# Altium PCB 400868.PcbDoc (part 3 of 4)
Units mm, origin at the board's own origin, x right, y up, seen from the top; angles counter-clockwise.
Board outline 117 x 63.5 mm, 4 copper layers (Top Layer, Mid-Layer 1, Mid-Layer 2, Bottom Layer), stack 1.58 mm thick; 211 components, 153 nets, 878 pads, 1351 vias.
Unrouted connection lines stored in the file: 16.
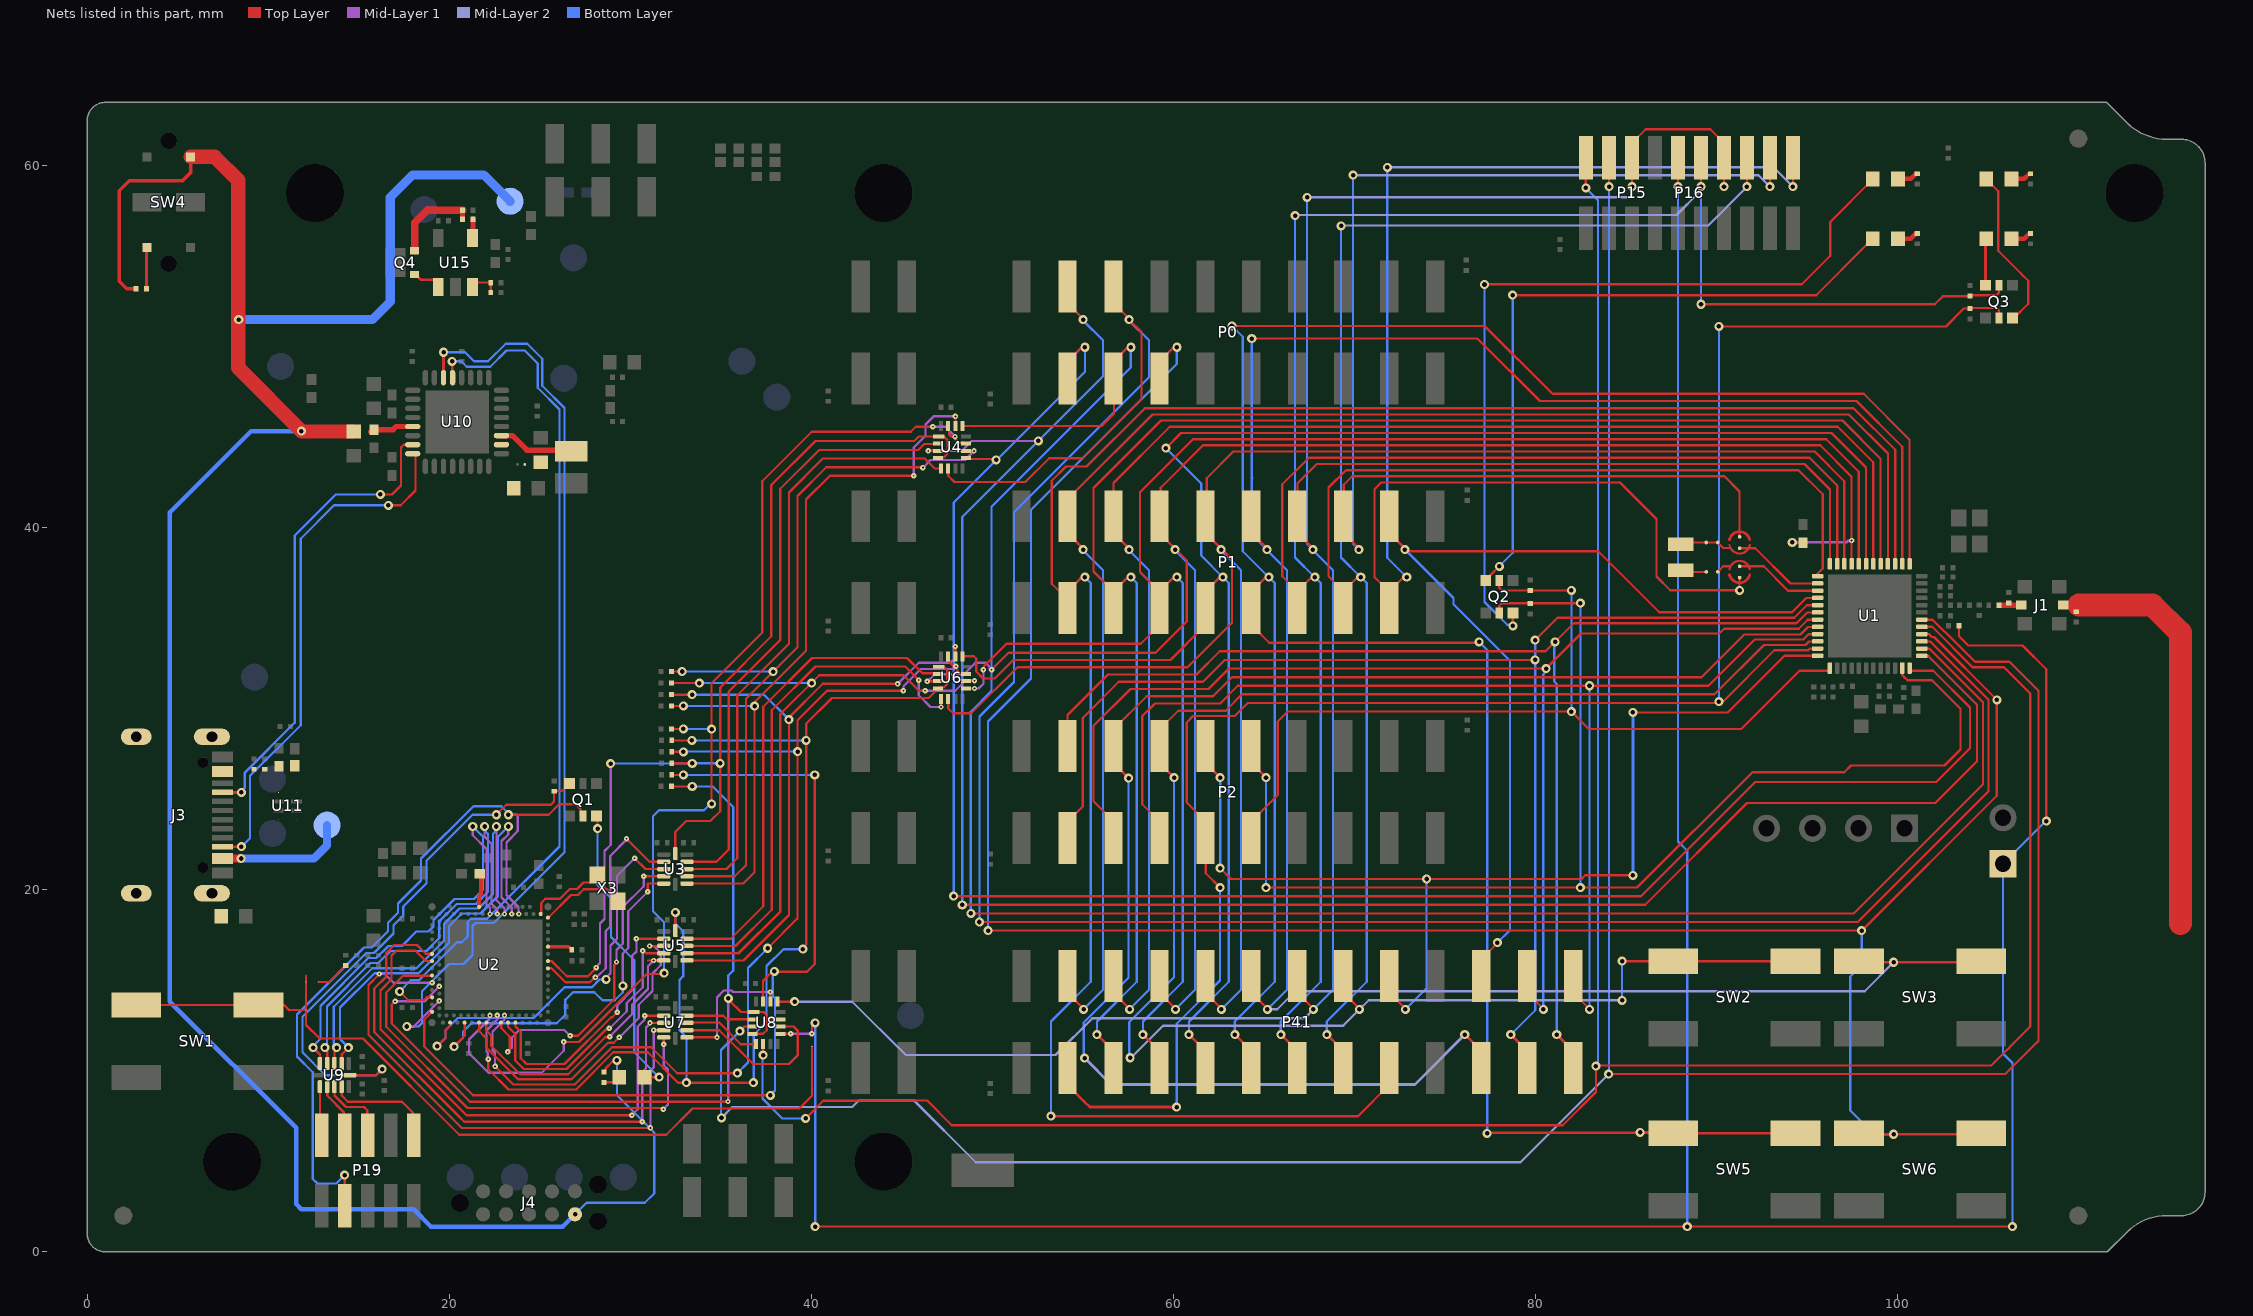
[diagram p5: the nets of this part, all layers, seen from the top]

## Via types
v1: diameter 0.5, hole 0.25, Top Layer to Bottom Layer, tented both sides, 1252 vias
v2: diameter 0.3, hole 0.1, Top Layer to Mid-Layer 1, tented top, 72 vias
v3: diameter 0.3, hole 0.1, Top Layer to Mid-Layer 1, tented both sides, 18 vias
v4: diameter 0.5, hole 0.25, Top Layer to Bottom Layer, tented bottom, 9 vias

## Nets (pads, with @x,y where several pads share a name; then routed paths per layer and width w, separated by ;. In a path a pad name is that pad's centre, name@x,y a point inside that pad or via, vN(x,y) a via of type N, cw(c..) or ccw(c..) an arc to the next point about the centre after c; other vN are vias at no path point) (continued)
NetC45_2: C45.2 U2.A13 | length 1.9
  Top Layer w0.225: U2.A13@21.66,19.064 21.66,19.644 21.77,19.754 C45.2@21.77,20.891
NetC59_1: C59.1 J3.SHLD
NetC82_1: C82.1 R48.2 U15.3 | length 1.7
  Top Layer w0.125: U15.3@21.3,53.3 21.3,53.313 21.538,53.55 C82.1@22.3,53.55 R48.2@22.3,53
NetL8_2: L8.2 U10.3 | length 4.2
  Top Layer w0.3: U10.3@22.892,45.096 23.492,45.096 24.292,44.296 L8.2@26.749,44.296
NetLD1_1: LD1.1 Q1.6 | length 16.7
  Top Layer w0.125: Q1.6@28.151,24.083 28.204,24.03 v1(28.204,23.381) ; LD1.1@30.865,9.716 30.929,9.652 v1(31.6,9.652)
  Top Layer w0.15: LD1.1@30.802,9.652 LD1.1@30.865,9.716
  Bottom Layer w0.125: v1(28.204,23.381) 28.204,20.271 28.942,19.533 28.942,17.39 30.225,16.107 30.225,11.027 v1(31.6,9.652)
NetLD1_2: LD1.2 R5.1 | length 1.4
  Top Layer w0.125: LD1.2@29.12,9.937 LD1.2@29.405,9.652
  Top Layer w0.15: R5.1@28.56,9.367 29.12,9.367 LD1.2@29.405,9.652
NetLD2_1: LD2.1 Q2.6 | length 45.3
  Top Layer w0.125: v1(77.2,53.441) 77.209,53.45 94.725,53.45 96.3,55.025 96.3,56.898 98.651,59.25 LD2.1@98.651,59.275 ; v1(78.767,34.579) Q2.6@78.767,35.289
  Bottom Layer w0.125: v1(77.2,53.441) 77.2,35.9 78.46,34.64 78.706,34.64 v1(78.767,34.579)
NetLD2_2: LD2.2 R19.1 | length 1.2
  Top Layer w0.25: LD2.2@100.048,59.275 100.746,59.275 101.021,59.55 101.09,59.55 R19.1@101.1,59.56
NetLD3_1: LD3.1 Q3.6 | length 8.9
  Top Layer w0.125: LD3.1@104.914,59.275 104.914,59.25 105.575,58.588 105.575,55.3 106.845,54.03 ; Q3.6@106.482,51.625 107.232,52.375 107.232,53.643 106.843,54.032
NetLD3_2: LD3.2 R20.1 | length 1.2
  Top Layer w0.25: LD3.2@106.311,59.275 107.008,59.275 107.283,59.55 107.352,59.55 R20.1@107.362,59.56
NetLD4_1: LD4.1 Q2.3 | length 37.5
  Top Layer w0.125: Q2.3@77.504,37.089 77.504,37.363 v1(78.017,37.875) ; v1(78.75,52.85) 95.527,52.85 98.308,55.631 98.333,55.631 98.651,55.95 LD4.1@98.651,55.975
  Bottom Layer w0.125: v1(78.017,37.875) 78.767,38.625 78.767,52.833 v1(78.75,52.85)
NetLD4_2: LD4.2 R21.1 | length 1.2
  Top Layer w0.25: LD4.2@100.048,55.975 100.746,55.975 101.021,56.25 101.09,56.25 R21.1@101.1,56.26
NetLD5_1: LD5.1 Q3.3 | length 2.6
  Top Layer w0.15: Q3.3@104.875,53.4 104.875,55.936 LD5.1@104.914,55.975
NetLD5_2: LD5.2 R22.1 | length 1.2
  Top Layer w0.25: LD5.2@106.311,55.975 107.008,55.975 107.283,56.25 107.352,56.25 R22.1@107.362,56.26
NetQ1_3: Q1.3 R8.1 U9.12 | length 30.6
  Top Layer w0.125: U9.12@14.514,9.765 15.965,9.765 v1(16.3,10.1) ; v1(22.608,24.15) 23.158,24.7 25.625,24.7 25.8,24.875 R8.1@25.8,25.449 ; R8.1@25.8,25.455 26.223,25.455 26.478,25.71 Q1.3@26.651,25.71
  Bottom Layer w0.125: v1(16.3,10.1) 15.965,9.765 13.16,9.765 11.9,11.025 11.9,12.983 15.429,16.512 15.848,16.512 16.925,17.589 16.925,18.05 17.463,18.588 17.463,19.081 18.753,20.372 18.753,21.603 21.3,24.15 v1(22.608,24.15)
NetQ4_1: Q4.1 U15.1 | length 1.7
  Top Layer w0.15: Q4.1@18.1,54 18.15,54 18.45,53.7 19.175,53.7 19.4,53.475 U15.1@19.4,53.3
NetQ4_2: Q4.2 R25.1 R35.2 | length 5
  Top Layer w0.27: R35.2@20.75,57.05 R25.1@20.75,57.55
  Top Layer w0.4: Q4.2@18.1,55.3 18.1,56.85 18.8,57.55 R25.1@20.75,57.55
NetR7_1: R7.1 U2.L31 | length 1.4
  Top Layer w0.187: U2.L31@25.46,16.864 26.598,16.864 26.719,16.743 26.734,16.743 26.775,16.702 R7.1@26.775,16.687
NetR23_1: R23.1 SB8.2 | length 1.9
  Top Layer w0.125: SB8.2@12.8,14.91 13.38,14.91 14.285,15.815 R23.1@14.3,15.815
NetR32_1: R32.1 U3.7 U4.14 | length 42.3
  Top Layer w0.125: R32.1@32.301,30.158 v1(32.941,30.158) ; U3.7@33.14,20.35 36.256,20.35 36.872,20.966 ; v1@36.872,30.153 36.872,30.358 39.722,33.208 39.722,41.563 41.037,42.877 v2(45.672,42.877) ; 36.875,20.966 v1(36.875,30.153) ; U4.14@47.968,45.632 U4.14@47.975,45.625 v2(47.974,46.156)
  Mid-Layer 1 w0.125: v2(45.672,42.877) 45.672,44.437 46.322,45.088 46.322,45.713 46.766,46.156
  Mid-Layer 1 w0.127: 46.766,46.156 v2(47.974,46.156)
  Bottom Layer w0.125: v1(32.941,30.158) v1@36.872,30.158
NetR35_1: R35.1 U15.4 | length 1.1
  Top Layer w0.27: U15.4@21.3,56 21.32,56.02 R35.1@21.32,57.05
NetR36_1: R36.1 SW4.3 | length 2.3
  Top Layer w0.15: R36.1@3.285,53.2 3.285,55.452 SW4.3@3.321,55.488
NetR56_1: R56.1 U5.7 U6.14 | length 36.4
  Top Layer w0.125: R56.1@32.301,30.783 v1(33.428,30.783) ; U5.7@33.14,16.1 36.26,16.1 38.775,18.615 38.775,29.523 40.64,31.388 44.762,31.388 v2(44.775,31.375) ; U6.14@47.954,32.918 U6.14@47.961,32.911
  Top Layer w0.127: U6.14@47.961,32.911 v2@47.961,33.442
  Mid-Layer 1 w0.125: v2(44.775,31.375) 45.952,32.552 47.288,32.552 47.289,32.553
  Mid-Layer 1 w0.127: 47.289,32.553 47.704,32.553 47.974,32.823 v2@47.974,33.431
  Bottom Layer w0.125: v1(33.428,30.783) 37.397,30.783 v1(38.775,29.405)
  other v2: 47.96,33.442
NetSB3_2: SB3.2 X2.2 | length 1.4
  Top Layer w0.125: X2.2@88.05,39.095 88.144,39.189 SB3.2@89.456,39.189
NetSB4_2: SB4.2 X2.1 | length 1.4
  Top Layer w0.125: X2.1@88.05,37.645 88.131,37.563 SB4.2@89.456,37.563
NetU2_B30: U2.B30 X3.3 | length 4.4
  Top Layer w0.125: U2.B30@25.06,18.664 25.079,18.684 25.079,18.754 25.085,18.76 25.085,19.273 25.315,19.502 26.123,19.502 26.67,20.05 27.075,20.05 27.125,20.1 27.431,20.406 27.818,20.406 28.181,20.769 X3.3@28.181,20.819
NetU2_C31: U2.C31 X3.1 | length 4.3
  Top Layer w0.125: U2.C31@25.46,18.464 25.485,18.464 26.735,19.715 27.126,19.715 27.443,20.031 27.747,20.031 28.718,20.031 X3.1@29.031,19.719
NetU3_10: U3.10 U4.2 | length 33.4
  Top Layer w0.125: U3.10@33.14,21.55 34.769,21.55 35.447,22.228 ; 35.45,22.228 35.45,30.951 38.297,33.798 38.297,42.153 40.447,44.302 45.923,44.302 46.252,44.632 46.981,44.632 U4.2@47,44.65
NetU5_10: U5.10 U6.2 | length 27.1
  Top Layer w0.125: U5.10@33.14,17.3 35.562,17.3 37.35,19.088 37.35,30.113 40.049,32.813 45.3,32.813 46.152,31.961 46.863,31.961 46.875,31.949 U6.2@46.985,31.949
NetU7_7: U7.7 U8.14 | length 7.5
  Top Layer w0.127: U7.7@33.14,11.85 v2(34.8,11.85) ; U8.14@37.745,13.825 v2@37.745,14.355
  Mid-Layer 1 w0.127: v2(34.8,11.85) 34.8,14.059 35.179,14.439 35.607,14.439 35.689,14.356 v2(37.744,14.356)
NetU7_8: U7.8 U8.10 | length 9.5
  Top Layer w0.127: U7.8@33.14,12.25 34.926,12.25 36.801,10.375 38.772,10.375 39.27,10.873 39.27,12.2 39.02,12.45 U8.10@38.32,12.45
NetU7_9: U7.9 U8.5 | length 4.3
  Top Layer w0.125: U7.9@33.14,12.65 33.16,12.67 34.925,12.67 36.12,11.475 U8.5@36.945,11.475
NetU7_10: U7.10 U8.2 | length 3.7
  Top Layer w0.125: U7.10@33.14,13.05 35.149,13.05 35.349,12.85 U8.2@36.77,12.85
nRF54_NRESET: P3.1 P15.10 P16.10 R1.2 SB1.1 U8.9 | length 177.4
  Top Layer w0.125: U8.9@38.32,12.05 38.321,12.051 v2(38.872,12.051) ; v2(40.045,12.05) 40.045,12.47 v1(40.225,12.65) ; v1@40.148,1.4 v1(88.4,1.4) v1@106.4,1.4 ; v1(87.89,58.844) P15.10@87.89,60.509 ; R1.2@103.411,34.579 103.411,34.011 103.923,33.5 106.925,33.5 108.238,32.187 v1(108.238,23.8)
  Mid-Layer 1 w0.125: v2(38.872,12.051) v2@40.044,12.051
  Bottom Layer w0.125: v1(40.224,1.4) 40.225,1.401 v1(40.225,12.65) ; v1(87.89,58.844) 87.89,22.671 88.4,22.161 v1(88.4,1.4) ; v1(106.364,1.4) 106.364,10.436 105.845,10.955 P3.1@105.845,21.443 108.202,23.8 v1(108.238,23.8)
P0.00: P0.3 U1.24 U4.9 | length 101.8
  Top Layer w0.125: v1(47.875,19.65) 85.85,19.65 92.162,25.962 102.16,25.962 104.025,27.827 104.025,30.075 101.995,32.105 U1.24@100.68,32.105 ; U4.9@48.55,43.85 48.597,43.803 50.172,43.803 v1(50.225,43.75) ; P0.3@54.363,49.386 54.88,49.903
  Bottom Layer w0.125: v1(47.875,19.65) 47.875,41.4 v1(50.225,43.75) 50.25,43.75 55.125,48.625 v1(55.125,49.975)
P0.01: P0.4 U1.25 U4.3 | length 111.3
  Top Layer w0.125: v1(48.35,19.175) 86.075,19.175 91.7,24.8 102.1,24.8 104.403,27.103 104.403,30.231 101.755,32.878 101.755,32.891 101.717,32.93 U1.25@101.505,32.93 ; P0.4@54.164,52.413 P0.4@54.189,52.388 ; P0.4@54.189,53.223 P0.4@54.189,52.388 ; v1@55.025,51.552 P0.4@54.189,52.388
  Top Layer w0.127: v2(46.469,44.25) U4.3@47,44.25
  Mid-Layer 1 w0.127: v2(46.469,44.25) 48.325,44.25 48.875,44.8 v1(52.55,44.8)
  Bottom Layer w0.125: v1(48.35,19.175) 48.35,40.6 v1(52.55,44.8) 56.125,48.375 56.125,50.356 v1@55.025,51.456
  other v1: 55.025,51.5
P0.02: P0.5 U1.26 U4.13 | length 114.6
  Top Layer w0.125: U4.13@48.375,45.625 56.037,45.625 56.729,46.317 P0.5@56.729,48.778 ; v1(48.825,18.7) 97.6,18.7 104.733,25.833 104.733,30.367 101.78,33.32 101.515,33.32 U1.26@101.505,33.33 ; P0.5@56.903,49.386 57.42,49.903
  Bottom Layer w0.125: v1(48.825,18.7) 48.825,29.842 49.962,30.98 49.962,41.162 57.665,48.865 v1(57.665,49.975)
P0.03: P0.6 U1.27 U4.6 | length 126.1
  Top Layer w0.125: U4.6@47.575,43.275 47.575,42.875 47.925,42.525 51.825,42.525 53.15,43.85 55,43.85 58.25,47.1 58.25,50.815 v1(57.565,51.5) ; v1(49.3,18.225) 97.825,18.225 105.047,25.447 105.047,30.498 101.824,33.72 101.515,33.72 U1.27@101.505,33.73 ; P0.6@56.704,52.413 P0.6@56.729,52.388 ; P0.6@56.729,53.223 P0.6@56.729,52.388 ; v1@57.6,51.517 P0.6@56.729,52.388
  Bottom Layer w0.125: v1(49.3,18.225) 49.3,29.575 51.213,31.488 51.213,40.863 58.665,48.315 58.665,50.356 v1@57.565,51.456
P0.04: P0.7 SW6.2 U1.28 | length 127.9
  Top Layer w0.125: v1(49.775,17.75) 98.05,17.75 105.5,25.2 v1(105.5,30.5) 102.03,33.97 101.91,33.97 101.751,34.13 U1.28@101.505,34.13 ; P0.7@59.443,49.386 59.96,49.903 ; SW6.2@96.887,6.558 96.945,6.5 103.579,6.5 SW6.2@103.637,6.558
  Top Layer w0.15: P0.7@59.269,47.549 P0.7@59.269,48.578
  Bottom Layer w0.125: v1(49.775,17.75) 49.775,29.3 52.15,31.675 52.15,41 60.205,49.055 v1(60.205,49.975) ; v1(98.034,17.75) 98.034,15.841 97.4,15.207 97.4,7.815 98.715,6.5 v1(99.8,6.5)
P1.00: P1.3 P41.17 U1.39 | length 114.4
  Top Layer w0.125: v1@53.3,7.5 70.211,7.5 P41.17@71.944,9.233 ; P1.3@54.164,35.56 54.164,36.039 53.3,36.903 53.3,42.6 54.085,43.385 55.214,43.385 58.438,46.609 97.591,46.609 99.89,44.31 U1.39@99.89,38.164
  Top Layer w0.15: P1.3@54.164,36.039 54.164,36.487 54.885,37.208 55.058,37.208 v1(55.125,37.275)
  Bottom Layer w0.125: 53.25,7.8 53.25,12.725 55.45,14.925 55.45,36.95 v1(55.125,37.275)
  other v1: 53.25,7.5
P1.01: P1.4 P41.4 U1.40 | length 85.7
  Top Layer w0.125: P41.4@54.164,15.24 54.164,14.313 55.05,13.427 v1(55.05,13.4) ; v1(55.025,38.8) 55.025,38.852 54.164,39.713 P1.4@54.164,40.64 54.2,40.676 54.2,41.603 54.597,42 58.864,46.267 97.329,46.267 99.49,44.105 U1.40@99.49,38.165
  Bottom Layer w0.125: v1(55.025,38.8) 55.025,38.756 56.125,37.656 56.125,14.475 v1(55.05,13.4)
P1.02: P1.5 P41.5 U1.41 | length 87.6
  Top Layer w0.125: P1.5@56.704,35.56 P1.5@56.704,36.487 ; v1(57.665,37.275) 57.593,37.203 57.42,37.203 P1.5@56.704,36.487 ; U1.41@99.08,38.155 99.08,43.82 96.976,45.924 59.324,45.924 55.6,42.2 55.6,37.591 P1.5@56.704,36.487
  Top Layer w0.15: v1@55.791,12 P41.5@56.704,11.087
  Bottom Layer w0.125: v1(55.79,12) 55.79,12.725 57.99,14.925 57.99,36.95 v1(57.665,37.275)
P1.03: P1.6 P41.6 U1.42 | length 80.1
  Top Layer w0.125: P41.6@56.704,14.313 v1@57.59,13.427 ; P1.6@56.704,39.713 v1@57.565,38.852 ; P1.6@56.704,40.64 56.704,42.475 59.811,45.582 96.718,45.582 98.68,43.62 U1.42@98.68,38.155
  Bottom Layer w0.125: v1@57.565,38.756 58.665,37.656 58.665,14.475 v1(57.59,13.4)
  other v1: 57.565,38.8
P1.04: P1.7 P41.7 U1.44 U6.9 | length 96
  Top Layer w0.125: U6.9@48.55,31.125 v2(49.025,31.125) ; v2(49.517,32.163) 49.551,32.196 49.551,32.351 50.8,33.6 58.211,33.6 59.244,34.633 P1.7@59.244,35.56 59.244,36.259 59.443,36.458 59.443,36.686 59.96,37.203 60.133,37.203 v1(60.205,37.275) ; P1.7@59.244,36.487 58.17,37.561 58.17,41.97 61.097,44.897 96.084,44.897 97.88,43.1 U1.44@97.88,38.155
  Top Layer w0.15: v1@58.331,12 P41.7@59.244,11.087
  Mid-Layer 1 w0.125: v2(49.025,31.125) 49.026,31.126 49.251,31.126 49.517,31.392 v2(49.517,32.163)
  Bottom Layer w0.125: v1(58.33,12) 58.33,12.725 60.53,14.925 60.53,36.95 v1(60.205,37.275)
P1.05: C41.2 P1.8 P41.8 U1.45 U6.3 | length 101.5
  Top Layer w0.125: v2(49.967,32.163) 50.905,33.1 59.025,33.1 60.75,34.825 60.75,38.2 v1@60.101,38.849 ; P41.8@59.244,14.313 v1@60.13,13.427 ; P1.8@59.244,39.713 59.504,39.454 59.693,39.264 v1@60.105,38.852 ; P1.8@59.244,40.64 59.244,39.706 59.5,39.45 59.507,39.45 59.69,39.267 P1.8@59.69,39.26 ; P1.8@59.309,40.363 59.309,42.209 61.655,44.555 95.745,44.555 97.48,42.82 v2(97.48,39.3) ; v2@97.409,39.309 97.409,39.262 97.48,39.19 U1.45@97.48,38.155
  Top Layer w0.127: v2(46.414,31.514) 46.426,31.525 U6.3@47,31.525
  Top Layer w0.15: v1(94.2,39.2) C41.2@94.779,39.2 ; C41.2@94.779,39.3 C41.2@94.804,39.275
  Mid-Layer 1 w0.127: v2(46.414,31.514) 46.425,31.514 46.825,31.914 48.439,31.914 49.064,32.539 49.639,32.539 49.856,32.322 49.856,32.178 v2@49.889,32.145 ; v2@49.964,32.167 v2(49.967,32.163)
  Mid-Layer 1 w0.15: v1(94.2,39.2) 97.2,39.2 97.271,39.271 97.389,39.271 v2@97.418,39.3
  Bottom Layer w0.125: v1@60.105,38.756 61.205,37.656 61.205,14.475 v1(60.13,13.4)
  other v1: 60.105,38.8
P1.06: P1.9 P41.9 U1.43 U6.13 | length 98.7
  Top Layer w0.125: U6.13@48.361,32.911 48.989,32.911 49.118,32.782 49.118,32.057 49.495,31.68 50.144,31.68 51.164,32.7 59.851,32.7 P1.9@61.655,34.504 ; v1(59.6,44.4) 60.439,45.239 96.371,45.239 98.28,43.33 U1.43@98.28,38.155 ; P1.9@61.784,35.56 61.825,35.601 61.825,35.675 61.85,35.65 61.85,36.553 62.5,37.203 62.673,37.203 v1(62.745,37.275)
  Top Layer w0.15: v1@60.871,12 P41.9@61.784,11.087
  Bottom Layer w0.125: v1(59.6,44.4) 61.55,42.45 61.55,38.47 v1(62.745,37.275) 63.07,36.95 63.07,14.925 60.87,12.725 v1(60.87,12)
P1.07: P1.10 P41.10 U1.46 U6.6 | length 94.8
  Top Layer w0.125: U6.6@47.575,30.55 47.575,30.025 47.85,29.75 48.85,29.75 51.4,32.3 60.795,32.3 63.25,34.755 63.25,38.247 P1.10@61.784,39.713 ; P41.10@61.784,14.313 v1@62.67,13.427 ; P1.10@61.849,40.363 61.849,42.739 63.322,44.212 95.438,44.212 97.08,42.57 U1.46@97.08,38.155
  Bottom Layer w0.125: v1@62.645,38.756 63.745,37.656 63.745,14.475 v1(62.67,13.4)
  other v1: 62.645,38.8
P1.08: P1.11 P41.11 SW5.2 U1.37 | length 146.2
  Top Layer w0.125: v1(63.25,51.15) 77.2,51.15 80.95,47.4 98.149,47.4 100.68,44.869 U1.37@100.68,38.155 ; P1.11@64.39,36.553 65.04,37.203 ; P1.11@64.462,34.495 65.307,33.65 76.85,33.65 v1(76.9,33.7) ; v1(77.35,6.55) 77.375,6.575 85.775,6.575 v1(85.8,6.6)
  Top Layer w0.15: v1@63.411,12 P41.11@64.324,11.087 ; v1(85.8,6.6) 87.583,6.6 SW5.2@87.625,6.558 SW5.2@93.375,6.558
  Bottom Layer w0.125: v1(63.25,51.15) 63.85,50.55 63.85,38.71 v1(65.285,37.275) 65.61,36.95 65.61,14.925 63.41,12.725 v1(63.41,12) ; v1(76.9,33.7) 77.35,33.25 v1(77.35,6.55)
P1.09: P1.12 P41.12 SW3.2 U1.38 | length 127
  Top Layer w0.125: P41.12@64.324,14.313 v1@65.21,13.427 ; P1.12@64.324,39.713 v1@65.185,38.852 ; v1(64.343,50.457) 76.805,50.457 80.262,47 97.755,47 100.28,44.474 U1.38@100.28,38.155
  Top Layer w0.152: SW3.2@97.887,16.058 97.945,16 103.579,16 SW3.2@103.637,16.058
  Mid-Layer 2 w0.125: v1(65.21,13.4) 65.75,13.4 66.75,14.4 98.2,14.4 v1(99.8,16)
  Bottom Layer w0.125: v1(64.343,50.457) 64.343,42.692 ; 64.389,42.739 64.343,42.692 ; v1@65.185,38.756 66.285,37.656 66.285,14.475 v1(65.21,13.4) ; v1(65.185,38.8) 64.343,39.642 64.343,42.692
P1.10: P1.13 P16.12 P41.13 Q3.2 R11.1 U1.47 | length 140.1
  Top Layer w0.125: P1.13@66.889,36.195 66.419,36.666 66.419,36.933 66.032,37.319 66.032,42.403 67.499,43.87 95.149,43.87 96.68,42.338 U1.47@96.68,38.155 ; P1.13@66.93,36.553 67.58,37.203 ; v1(89.16,52.35) 102.077,52.35 102.497,52.77 ; v1(89.16,58.844) P16.12@89.16,60.509 ; 102.522,52.794 103.996,52.794 R11.1@104.02,52.819 ; R11.1@103.923,52.855 105.479,52.855 105.625,53 Q3.2@105.625,53.4
  Top Layer w0.15: v1@65.951,12 P41.13@66.864,11.087
  Mid-Layer 2 w0.125: v1(66.735,57.246) 66.764,57.275 87.8,57.275 89.088,58.563 89.088,58.772 v1(89.16,58.844)
  Bottom Layer w0.125: v1(65.95,12) 65.95,12.725 68.15,14.925 68.15,36.95 v1(67.825,37.275) 66.735,38.365 v1(66.735,57.246) ; v1(89.16,52.35) v1(89.16,58.844)
P1.11: P1.14 P15.6 P16.6 P16.14 P41.14 U1.48 U8.13 | length 146.3
  Top Layer w0.125: U8.13@38.145,13.825 v1(39.095,13.825) ; P41.14@66.864,14.313 v1@67.75,13.427 ; P1.14@66.864,39.713 v1@67.725,38.852 ; P1.14@66.87,39.775 66.864,39.781 P1.14@66.864,40.64 66.864,42.464 67.927,43.527 94.873,43.527 96.28,42.12 U1.48@96.28,38.155 ; v1(85.35,58.844) 85.35,61.27 86.105,62.025 89.675,62.025 90.43,61.27 v1(90.43,58.844)
  Mid-Layer 2 w0.125: v1(39.095,13.825) 42.275,13.825 45.225,10.875 53.5,10.875 55.525,12.9 67.25,12.9 v1(67.75,13.4) ; v1(67.4,58.259) 85.209,58.259 85.35,58.4 v1(85.35,58.844)
  Bottom Layer w0.125: v1(67.4,58.259) 67.4,39.125 v1(67.725,38.8) ; v1@67.725,38.756 68.825,37.656 68.825,14.475 v1(67.75,13.4)
P1.12: P1.15 P16.16 P41.15 U1.1 | length 112.7
  Top Layer w0.125: P1.15@69.429,36.195 68.959,36.666 68.959,36.941 68.582,37.318 68.582,42.223 69.544,43.185 94.55,43.185 95.88,41.854 95.88,37.755 U1.1@95.455,37.33 ; P1.15@69.47,36.553 70.12,37.203 ; v1(91.7,58.844) P16.16@91.7,60.509
  Top Layer w0.15: v1@68.491,12 P41.15@69.404,11.087
  Mid-Layer 2 w0.125: v1(69.275,56.675) 69.3,56.7 89.556,56.7 v1(91.7,58.844)
  Bottom Layer w0.125: v1(68.49,12) 68.49,12.725 70.69,14.925 70.69,36.95 v1(70.365,37.275) 69.275,38.365 v1(69.275,56.675)
P1.13: P1.16 P16.18 SB5.2 | length 73.6
  Top Layer w0.125: P1.16@69.404,39.713 v1@70.265,38.852 ; P1.16@69.429,40.64 69.429,42.379 69.892,42.842 90.458,42.842 91.292,42.008 SB5.2@91.292,39.501 ; v1(92.97,58.844) P16.18@92.97,60.509
  Mid-Layer 2 w0.125: v1(69.94,59.479) 69.943,59.476 92.338,59.476 v1(92.97,58.844)
  Bottom Layer w0.125: v1(69.94,59.479) 69.94,39.125 v1(70.265,38.8)
P1.13/XL1: SB3.1 SB5.1 U1.2 | length 5.8
  Top Layer w0.125: SB3.1@90.081,39.189 90.384,38.886 90.789,38.886 ; SB5.1@91.292,38.877 91.791,38.877 92.159,38.877 94.106,36.93 U1.2@95.455,36.93
P1.14: P1.17 P16.20 SB6.2 | length 80.5
  Top Layer w0.125: P1.17@71.969,35.878 71.969,36.462 71.499,36.933 71.467,36.933 71.125,37.275 71.125,42.125 71.5,42.5 84.687,42.5 86.7,40.487 86.7,37.311 87.463,36.547 v1(91.292,36.547) SB6.2@91.292,37.251 ; P1.17@72.01,36.553 72.66,37.203 ; v1(94.24,58.844) P16.20@94.24,60.509
  Mid-Layer 2 w0.125: v1(71.83,59.913) 93.17,59.913 v1(94.24,58.844)
  Bottom Layer w0.125: v1(71.83,59.913) 71.83,38.35 v1(72.905,37.275)
P1.14/XL2: SB4.1 SB6.1 U1.3 | length 5.6
  Top Layer w0.125: SB4.1@90.081,37.563 90.394,37.876 90.794,37.876 ; SB6.1@91.292,37.875 91.791,37.875 92.621,37.875 93.966,36.53 U1.3@95.455,36.53
P1.15: P1.18 P41.22 U1.4 | length 53.5
  Top Layer w0.125: P1.18@71.944,39.713 v1@72.805,38.852 ; P1.18@71.95,39.707 v1@72.805,38.852 ; P41.22@77.024,16.167 v1@77.91,17.053 ; U1.4@95.455,36.13 95.446,36.12 94.978,36.12 94.188,35.33 86.85,35.33 83.48,38.7 72.957,38.7 v1@72.805,38.852
  Top Layer w0.15: P41.22@77.024,15.24 P41.22@77.024,16.167
  Bottom Layer w0.125: v1(72.805,38.8) 75.482,36.123 75.482,35.782 78.604,32.66 78.604,17.774 v1(77.91,17.08)
P1.16: P2.3 P41.23 U1.5 | length 73.1
  Top Layer w0.125: P2.3@54.164,22.86 54.164,23.787 54.61,24.233 54.633,24.233 55,24.6 55,29.5 57,31.5 61.655,31.5 62.855,32.7 v1@79.93,32.7 ; v1(80,33.8) 81.23,35.03 94.312,35.03 95.003,35.721 U1.5@95.446,35.721
  Top Layer w0.15: v1@78.651,12 P41.23@79.564,11.087
  Bottom Layer w0.125: v1(78.65,12) 80,13.35 80,32.47 v1@80.115,32.585 ; v1(80,32.7) v1(80,33.8)
P1.17: P2.4 P41.25 U1.6 | length 68.4
  Top Layer w0.125: P2.4@54.164,27.94 54.164,29.664 56.4,31.9 61.294,31.9 62.569,33.175 80.575,33.175 82.13,34.73 94.436,34.73 95.027,35.321 U1.6@95.446,35.321
  Top Layer w0.15: v1@81.191,12 P41.25@82.104,11.087
  Bottom Layer w0.125: v1(81.1,33.7) 81.05,33.65 81.05,31.512 81.19,31.373 v1(81.19,12)
P1.18: P2.5 P41.24 U1.7 | length 69.1
  Top Layer w0.125: P2.5@56.704,22.86 56.704,23.787 55.6,24.891 55.6,29.062 57.638,31.1 61.959,31.1 63.084,32.225 v1(80.6,32.225) 82.537,34.162 90.175,34.162 90.442,34.43 94.56,34.43 95.051,34.921 U1.7@95.446,34.921 ; P41.24@79.564,14.313 v1@80.45,13.427
  Bottom Layer w0.125: v1(80.45,13.4) 80.45,31.9 80.528,31.978 80.528,32.153 v1(80.6,32.225)
P1.19: P2.6 P41.21 U1.8 | length 83.8
  Top Layer w0.125: P2.6@56.704,27.013 57.54,26.177 v1(57.54,26.175) ; P2.6@56.704,27.94 56.704,28.867 58.537,30.7 62.2,30.7 63.25,31.75 89.19,31.75 91.545,34.105 94.66,34.105 95.075,34.52 95.446,34.52 U1.8@95.455,34.53
  Top Layer w0.15: v1@76.111,12 P41.21@77.024,11.087
  Mid-Layer 2 w0.15: v1(55.115,10.7) 56.565,9.25 73.36,9.25 v1(76.11,12)
  Bottom Layer w0.125: v1(55.115,10.7) 55.065,10.75 55.065,12.675 57.54,15.15 v1(57.54,26.175)
P1.20: P2.7 P41.26 U1.9 | length 65.3
  Top Layer w0.125: P2.7@59.244,22.86 59.244,23.787 58.3,24.731 58.3,29.6 59,30.3 62.6,30.3 63.575,31.275 v1(83,31.275) 89.575,31.275 92.13,33.83 94.809,33.83 95.099,34.12 95.446,34.12 U1.9@95.455,34.13 ; P41.26@82.104,14.313 v1@82.99,13.427
  Bottom Layer w0.125: v1(83,13.4) v1(83,31.275)
P1.21: P2.8 P41.16 SW2.2 U1.10 | length 98.2
  Top Layer w0.125: P2.8@59.244,27.013 60.05,26.207 v1(60.05,26.2) ; P2.8@59.244,27.94 59.244,28.867 60.277,29.9 62.9,29.9 63.8,30.8 89.912,30.8 92.642,33.53 94.933,33.53 95.124,33.72 95.446,33.72 U1.10@95.455,33.73 ; P41.16@69.404,14.313 v1@70.29,13.427
  Top Layer w0.15: v1(84.8,16.058) SW2.2@94.383,16.058
  Mid-Layer 2 w0.125: v1(57.625,10.725) 57.674,10.725 59.449,12.5 69.39,12.5 v1(70.29,13.4) 70.3,13.4 70.8,13.9 v1(84.8,13.9)
  Bottom Layer w0.125: v1(57.625,10.725) 57.575,10.775 57.575,12.7 60.05,15.175 v1(60.05,26.2) ; v1@84.8,13.962 v1(84.8,16.058)
P1.22: P2.9 P41.3 Q3.5 R27.1 U1.11 | length 104.1
  Top Layer w0.125: v1(62.59,20.125) 61.8,20.915 61.8,22.844 P2.9@61.784,22.86 61.784,23.787 60.75,24.821 60.75,29.25 61.1,29.6 63.4,29.6 64.125,30.325 90.3,30.325 93.205,33.23 95.08,33.23 95.171,33.32 95.446,33.32 U1.11@95.455,33.33 ; v1(90.15,51.125) 102.691,51.125 103.676,52.11 104.035,52.11 104.095,52.17 R27.1@104.095,52.185 ; R27.1@103.923,52.146 105.479,52.146 105.625,52 Q3.5@105.625,51.6
  Top Layer w0.15: P41.3@54.164,9.233 55.077,8.32 ; P41.3@54.164,10.16 P41.3@54.164,11.087 ; 55.079,8.32 55.399,8 v1(60.191,8)
  Bottom Layer w0.125: v1(60.191,8) 60.2,8.009 60.2,12.6 62.59,14.99 v1(62.59,20.125) ; v1(90.15,30.4) v1(90.15,51.125)
P1.23: P2.10 P41.18 U1.12 | length 58.6
  Top Layer w0.125: P2.10@61.784,27.013 v1@62.59,26.207 ; v1(62.6,21.2) 63.2,20.6 82.564,20.6 82.764,20.8 v1(85.4,20.8) ; P41.18@71.944,14.313 v1@72.83,13.427 ; v1(85.4,29.8) 90.638,29.8 93.768,32.93 ; 93.775,32.93 U1.12@95.455,32.93
  Bottom Layer w0.125: v1(62.59,26.2) 62.595,26.195 62.595,21.205 v1(62.6,21.2) ; v1(72.83,13.4) 74,14.57 v1(74,20.6)
  Bottom Layer w0.15: v1(85.4,20.8) v1(85.4,29.8)
P1.24: P2.11 Q2.2 R10.1 U1.13 | length 50.6
  Top Layer w0.125: P2.11@64.324,22.86 64.324,23.787 65.775,25.238 65.775,29.3 66.325,29.85 v1(82.001,29.85) 82.962,28.89 91.385,28.89 94.6,32.105 U1.13@96.28,32.105 ; Q2.2@78.017,37.089 78.017,36.689 78.162,36.543 R10.1@79.719,36.543 v1(82,36.543)
  Bottom Layer w0.125: v1@82,36.5 82.001,36.499 v1(82.001,29.85)
P1.25: P2.12 Q2.5 R12.1 U1.23 | length 75.8
  Top Layer w0.125: P2.12@64.324,27.013 v1@65.13,26.207 ; v1(65.13,20.125) v1(82.5,20.125) 85.625,20.125 92,26.5 97.072,26.5 97.441,26.869 102.612,26.869 103.5,27.756 103.5,30 101.926,31.575 100.579,31.575 100.552,31.601 100.535,31.601 100.38,31.756 100.38,31.766 100.28,31.866 U1.23@100.28,32.105 ; Q2.5@78.017,35.289 78.017,35.689 78.162,35.834 v1(82.5,35.834)
  Bottom Layer w0.125: v1(65.13,20.125) v1(65.13,26.2) ; v1(82.5,20.125) v1@82.5,35.8
PCBANT: C73.2 J1.3 | length 22.3
  Top Layer w1.27: 110.033,35.73 114.101,35.73 115.66,34.171 ; 115.66,18.15 115.66,34.221
PVSS1: C24.1 C27.1 NT2.2 U10.2
RESET_BUTTON: SB1.2 SB2.1 SB8.1 SW1.2 | length 47
  Top Layer w0.125: SW1.2@1.963,13.637 10.888,13.637 11.161,13.364 SB2.1@12.1,13.364 ; 12.1,14.864 SB2.1@12.1,13.364 ; SB8.1@12.1,14.91 12.1,15.273 ; SB1.2@40.045,11.35 40.045,8.62 39.35,7.925 33.45,7.925 32,6.475 20.561,6.475 15.249,11.787 12.85,11.787 12.1,12.537 SB2.1@12.1,13.364
RF: C9.2 J1.1 L4.2 | length 1.2
  Top Layer w0.3: L4.2@105.741,35.73 106.2,35.73 J1.1@106.845,35.73 ; J1.1@106.79,35.786 J1.1@106.845,35.73
RTS0: U3.9 U4.5 | length 33.8
  Top Layer w0.125: U3.9@33.14,21.15 35.328,21.15 35.922,21.744 ; 35.922,30.752 38.772,33.602 38.772,41.956 40.644,43.827 46.046,43.827 ; 35.925,21.744 35.925,30.752
  Top Layer w0.127: 46.046,43.827 46.273,43.827 46.825,43.275 U4.5@47.175,43.275
RTS1: U5.9 U6.5 | length 28.8
  Top Layer w0.125: U5.9@33.14,16.9 35.825,16.9 37.825,18.9 37.825,29.916 40.246,32.338 45.203,32.338 v2(45.951,31.59) ; v2(47.175,30.1) U6.5@47.175,30.55
  Mid-Layer 1 w0.125: v2(45.951,31.59) 45.951,30.749 46.6,30.1 v2(47.175,30.1)
RxD0: R28.2 U3.8 U4.10 | length 42
  Top Layer w0.125: R28.2@32.285,32.063 v1(32.875,32.063) ; U3.8@33.14,20.75 35.781,20.75 36.397,21.366 ; 36.397,30.555 v1(37.904,32.061) 39.247,33.405 39.247,41.759 40.838,43.35 46.15,43.35 v2(46.175,43.325) ; 36.4,21.366 36.4,30.555 ; U4.10@48.55,44.25 v2(49,44.25)
  Mid-Layer 1 w0.125: v2(46.175,43.325) 46.6,43.75 48.5,43.75 v2(49,44.25)
  Bottom Layer w0.125: v1(32.875,32.063) v1(37.904,32.061) v1(37.904,32.061)
RxD1: R29.2 U5.8 U6.10 | length 37.5
  Top Layer w0.125: R29.2@32.285,31.428 33.822,31.428 v1(33.825,31.425) ; 38.3,18.798 38.3,29.72 40.443,31.863 45.1,31.863 45.962,31 v2(46.3,31) ; U6.10@48.55,31.525 48.562,31.537 49.012,31.537 v2(49.025,31.55)
  Top Layer w0.15: U5.8@33.14,16.5 36.002,16.5 38.3,18.798
  Mid-Layer 1 w0.125: v2(46.3,31) 47.964,31 48.514,31.55 v2(49.025,31.55)
  Bottom Layer w0.125: v1(33.825,31.425) 40.031,31.425 v1(40.032,31.426)
SWD0_CLK: U2.B18 U9.4 | length 24.2
  Top Layer w0.125: v1(13.139,11.29) 13.139,11.189 13.264,11.064 U9.4@13.264,10.405
  Mid-Layer 1 w0.125: v1(21.958,23.5) 21.958,22.942 22.35,22.55 22.35,19.239 22.66,18.928 v2(22.66,18.664)
  Bottom Layer w0.125: v1@13.025,11.25 13.025,11.286 13.25,11.511 13.25,13.553 15.652,15.955 16.091,15.955 16.761,16.625 18.75,16.625 19.45,17.325 19.45,18.25 20.425,19.225 21.487,19.225 22.153,19.891 22.153,23.089 22.03,23.212 22.03,23.428 v1(21.958,23.5)
SWD0_CLK_EXT: P19.4 U9.8 | length 3.1
  Top Layer w0.125: U9.8@13.264,9.125 13.264,8.636 14.2,7.7 14.2,6.484 P19.4@14.234,6.45
SWD0_IO: U2.B16 U9.5 | length 24.4
  Top Layer w0.125: v1(12.489,11.29) 12.489,11.286 12.864,10.911 U9.5@12.864,10.405
  Mid-Layer 1 w0.125: v1(21.308,23.5) 21.308,23.011 22.066,22.254 ; 22.067,22.254 22.067,19.204 22.26,19.01 v2(22.26,18.664)
  Bottom Layer w0.125: v1@12.375,11.25 12.375,11.254 12.893,11.772 12.893,13.585 15.538,16.23 15.977,16.23 16.647,16.9 17.397,16.9 18.19,17.694 18.849,17.694 19.137,17.982 19.137,18.341 20.296,19.5 21.373,19.5 21.878,20.005 21.878,22.93 21.771,23.038 21.767,23.038 21.308,23.496 v1(21.308,23.5)
SWD0_IO_EXT: P19.2 U9.7 | length 2.7
  Top Layer w0.125: U9.7@12.864,9.125 12.864,6.55 P19.2@12.964,6.45
SWD0_RESET: U2.B22 U9.2 | length 24.6
  Top Layer w0.125: U9.2@14.064,10.405 14.064,10.911 14.439,11.286 v1(14.439,11.29)
  Mid-Layer 1 w0.125: v1(23.275,23.5) 23.263,23.487 23.263,23.063 22.9,22.7 22.9,19.578 23.46,19.017 v2(23.46,18.664)
  Bottom Layer w0.125: v1(14.439,11.29) 13.975,11.754 13.975,13.5 15.875,15.4 18.314,15.4 19.993,17.079 19.993,17.993 20.699,18.699 21.738,18.699 22.703,19.663 22.703,22.928 v1(23.275,23.5)
SWD0_RESET_EXT: P19.10 U9.10 | length 6.1
  Top Layer w0.125: U9.10@14.064,9.125 14.064,8.636 14.4,8.3 17.4,8.3 18,7.7 18,6.494 P19.10@18.044,6.45
SWD0_SEL: P19.3 Q1.5 U2.B24 | length 42.6
  Top Layer w0.125: v1(23.275,24.15) 25.5,24.15 26.075,24.725 27,24.725 27.264,24.461 27.264,24.047 Q1.5@27.387,23.923
  Top Layer w0.15: P19.3@14.234,2.55 v1(14.234,4.246)
  Mid-Layer 1 w0.125: v1(23.275,24.15) 23.727,24.15 23.8,24.077 23.8,23.246 23.175,22.622 23.175,19.709 23.835,19.049 23.835,18.689 v2(23.86,18.664)
  Bottom Layer w0.125: v1(14.234,4.246) 13.763,3.775 12.725,3.775 12.475,4.025 12.475,9.925 11.6,10.8 11.6,13.113 15.303,16.816 15.722,16.816 16.621,17.715 16.621,18.176 17.175,18.73 17.175,19.24 18.455,20.519 18.455,21.73 21.35,24.625 22.882,24.625 23.275,24.232 v1(23.275,24.15)
SWD0_SWO: U2.B20 U9.3 | length 24
  Top Layer w0.125: U9.3@13.664,10.405 13.664,11.064 13.789,11.189 v1(13.789,11.29)
  Mid-Layer 1 w0.125: v1(22.608,23.5) 22.625,23.483 22.625,19.421 23.06,18.986 v2(23.06,18.664)
  Bottom Layer w0.125: v1@13.675,11.25 13.625,11.3 13.625,13.539 15.761,15.675 18.2,15.675 19.718,17.193 19.718,18.118 20.574,18.974 21.625,18.974 22.428,19.777 22.428,23.105 22.537,23.214 22.537,23.428 v1(22.608,23.5)
SWD0_SWO_EXT: P19.6 U9.9 | length 4
  Top Layer w0.125: U9.9@13.664,9.125 13.664,8.636 14.3,8 15.3,8 15.479,7.821 P19.6@15.479,6.425
SWD3_CLK: U2.R1 U7.2 | length 29.6
  Top Layer w0.125: U2.R1@19.06,16.064 18.715,16.064 18.125,16.655 17.105,16.655 16.825,16.375 16.825,15.065 16.205,14.445 16.205,12.304 20.959,7.55 v2(30.1,7.55) ; v2(30.813,13.05) U7.2@31.86,13.05
  Mid-Layer 1 w0.125: v2(30.1,7.55) 30.424,7.874 30.424,12.451 30.775,12.802 30.775,13.012 v2(30.813,13.05)
SWD3_CTRL: R39.2 U2.AB2 U8.1 U8.4 U8.11 | length 49.7
  Top Layer w0.125: R39.2@32.306,25.713 v1(33.433,25.713)
  Top Layer w0.127: v2(17.02,13.84) 16.832,13.651 16.832,12.619 21.15,8.3 35.4,8.3 v2@35.425,8.325 ; v1@35.45,14 35.45,13.92 36.12,13.25 U8.1@36.82,13.25 37.37,13.25 37.545,13.075 37.545,12.85 ; U8.4@36.769,12.051 U8.4@36.77,12.05 37.345,12.05 37.545,12.25 37.545,12.85 ; U8.11@38.32,12.85 37.545,12.85
  Mid-Layer 1 w0.125: v2(35.408,8.308) 35.417,8.317 35.417,13.992 v1(35.425,14)
  Mid-Layer 1 w0.127: v2(17.02,13.84) 18.636,13.84 v3(19.46,14.664)
  Bottom Layer w0.125: v1(33.433,25.713) 34.562,25.713 35.7,24.575 35.7,15.538 35.425,15.263 35.425,14.025 v1@35.45,14
SWD3_IO: U2.N1 U7.3 | length 30.8
  Top Layer w0.125: U2.N1@19.06,16.464 18.711,16.464 18.225,16.95 16.973,16.95 16.537,16.514 16.537,15.213 15.859,14.536 15.859,12.161 20.625,7.395
  Top Layer w0.127: 20.625,7.395 20.832,7.188 v2(30.675,7.188) ; v2(31.1,12.65) U7.3@31.86,12.65
  Mid-Layer 1 w0.127: v2(30.675,7.188) 30.675,9.95 30.875,10.15 30.875,12.393 31.1,12.618 v2(31.1,12.65)
SWD3_RESET: U2.AA1 U7.4 | length 30.5
  Top Layer w0.125: v2(16.145,15.352) 16.145,15.337 15.55,14.742 15.55,11.998 20.698,6.85 v2(31.125,6.85)
  Top Layer w0.127: v2(31.3,12.25) U7.4@31.86,12.25
  Mid-Layer 1 w0.125: v2(16.145,15.352) 16.448,15.352 16.936,14.864 v2(19.06,14.864) ; v2(31.125,6.85) 31.125,8
  Mid-Layer 1 w0.127: 31.125,8 31.125,10.014 31.3,10.189 v2(31.3,12.25)
SWD3_SWO: U2.W1 U7.5 | length 26.2
  Top Layer w0.125: U2.W1@19.06,15.264 19.056,15.26 17.46,15.26 16.525,14.325 16.525,12.436 21.011,7.95 31.775,7.95 v2@31.85,7.875 ; U7.5@31.86,11.85 31.862,11.848 v2(31.862,11.475)
  Mid-Layer 1 w0.125: v2(31.843,7.882) 32.1,8.139 32.1,10.075 31.862,10.313 v2(31.862,11.475)
SWDCLK: P15.4 P16.4 U1.30 U8.3 | length 161.2
  Top Layer w0.125: v1(36.07,12.2) 36.071,12.2 36.321,12.45 U8.3@36.77,12.45 ; v1(84.08,58.844) P15.4@84.08,60.509 ; v1@84.225,9.75 84.3,9.825 105.968,9.825 107.569,11.425 107.8,11.657 107.8,31 106.2,32.6 104.3,32.6 102.658,34.242 102.629,34.242 101.95,34.92 101.515,34.92 U1.30@101.505,34.93
  Mid-Layer 2 w0.125: v1(35.05,7.4) 35.649,7.999 42.271,7.999 42.634,8.363 45.687,8.363 49.1,4.95 79.183,4.95 v1(84.053,9.82)
  Bottom Layer w0.125: v1(35.05,7.4) 35.025,7.425 35.025,11.155 v1(36.07,12.2) ; v1(84.053,9.82) 84.08,9.847 v1(84.08,58.844)
SWDIO: P15.2 P16.2 U1.29 U8.6 | length 153.9
  Top Layer w0.125: v1(37.345,10.873) U8.6@37.345,11.475 ; v1(39.7,7.375) 40.675,8.35 42.525,8.35 42.538,8.363 46.412,8.363 47.775,7 81.525,7 83.354,8.829 v1(83.354,10.26) 83.394,10.3 105.2,10.3 106.07,11.17 106.09,11.17 106.2,11.28 106.2,11.3 107.35,12.45 107.35,30.85 105.9,32.3 104.164,32.3 101.934,34.53 U1.29@101.505,34.53 ; v1(82.8,58.775) 82.8,60.44 P15.2@82.81,60.45
  Bottom Layer w0.125: v1(37.345,10.873) 37.312,10.841 37.312,8.469 38.406,7.375 v1(39.7,7.375) ; v1(82.8,58.775) 83.475,58.1 83.475,10.482 83.354,10.361 v1(83.354,10.26)
SWO_CTRL: R17.2 U2.AJ1 U8.15 | length 52
  Top Layer w0.125: U2.AJ1@19.06,13.264 18.627,12.831 18.627,11.348 21.325,8.65 29.462,8.65 29.474,8.662 ; 29.474,8.65 v1@37.738,8.65 ; R17.2@32.301,26.35 v1(32.941,26.35) ; U8.15@37.345,13.825 37.345,14.971 37.874,15.5 v1(37.975,15.5) 38,15.475 39.768,15.475 40.2,15.907 v1(40.2,26.35) ; v1@37.738,8.662 v1(37.75,8.65)
  Bottom Layer w0.125: v1(32.941,26.35) v1@40.1,26.35 ; v1(37.75,8.65) 37.75,8.661 38,8.911 38,14.025 37.875,14.15 37.875,15.239 37.903,15.268 37.903,15.428 v1(37.975,15.5)
TWI0_SCL: U2.AF2 U10.14 | length 52.6
  Top Layer w0.15: U10.14@19.692,48.296 19.696,48.3 19.696,49.696 v1(19.7,49.7)
  Mid-Layer 1 w0.125: v1(17.672,12.451) 17.681,12.442 18.041,12.442 v3@19.454,13.855
  Bottom Layer w0.125: v1(17.672,12.451) 18.313,12.451 18.506,12.643 18.506,14.406 20,15.9 20.8,15.9 21.3,16.4 21.3,18.01 21.459,18.169 22.469,18.169 26.375,22.075 26.375,46.613 25.142,47.846 25.142,49.346 24.313,50.175 23.125,50.175 22.156,49.206 21.373,49.206 20.879,49.7 v1(19.7,49.7)
  other v3: 19.46,13.864
TWI0_SDA: U2.AE1 U10.13 | length 48.3
  Top Layer w0.125: v1(17.269,14.385) 17.748,13.906 18.603,13.906 18.761,14.064 U2.AE1@19.06,14.064
  Top Layer w0.15: v1(20.167,49.2) 20.179,49.187 20.179,48.309 U10.13@20.192,48.296
  Bottom Layer w0.125: v1(17.269,14.385) 17.884,15 18.335,15 20.435,17.1 20.7,17.1 21.027,17.427 21.027,18.227 21.2,18.4 22.1,18.4 26.101,22.401 26.101,46.534 24.892,47.743 24.892,49.083 24.175,49.8 23.175,49.8 22.274,48.899 20.98,48.899 20.679,49.2 v1(20.167,49.2)
UART0_CTRL: R13.2 U2.R31 U3.12 U4.1 U4.4 | length 57.6
  Top Layer w0.125: U2.R31@25.46,16.064 25.665,16.064 26.504,15.225 27.67,15.225 28.133,15.689 v2(28.133,15.707) ; R13.2@32.306,26.987 v1(33.433,26.987) ; U3.12@32.5,22 32.5,23.2 33.1,23.8 34.427,23.8 34.975,24.348 v1(34.975,26.987) 34.975,31.183 37.797,34.005 37.797,42.36 40.24,44.802 45.701,44.802 45.949,45.05 U4.1@47.05,45.05 ; U4.4@47,43.85 47.047,43.898 47.344,43.898 47.536,44.089 47.536,44.85 47.383,45.003 47.097,45.003 U4.1@47.074,45.025
  Mid-Layer 1 w0.125: v2(28.133,15.707) 28.133,15.754 28.337,15.958 28.337,18.144 28.588,18.394 28.588,22.15 28.928,22.49 v1(28.928,26.978)
  Bottom Layer w0.125: v1(28.928,26.978) 33.423,26.978 v1(33.433,26.987) v1@34.943,26.987
UART0_CTS: U2.AL9 U3.5 | length 20.6
  Top Layer w0.125: v1(20.28,11.34) 20.28,11.372 20.742,11.834 20.742,11.836 20.86,11.954 U2.AL9@20.86,12.664 ; v2(30.975,19.9) 30.98,19.905 30.98,20.345 30.985,20.35 U3.5@31.86,20.35
  Mid-Layer 1 w0.125: v1(29.6,14.7) 29.6,16.486 29.9,16.786 29.9,18.825 v2(30.975,19.9)
  Bottom Layer w0.125: v1(20.28,11.34) 20.775,11.836 20.775,12.167 21.233,12.625 25.955,12.625 26.425,13.095 26.425,13.927 26.848,14.35 28.025,14.35 28.475,13.9 29.15,13.9 29.591,14.341 29.591,14.691 v1(29.6,14.7)
UART0_HWFC: R14.2 U2.AK16 U4.11 U4.15 | length 63.8
  Top Layer w0.125: v2(26.34,11.6) 27.172,11.6 30.922,15.35 31.829,15.35 v1(31.876,15.397) ; R14.2@32.306,28.888 v1(32.946,28.888) ; v1@34.5,24.631 v1(34.5,28.881) 34.5,31.415 37.297,34.213 37.297,42.567 40.033,45.302 45.501,45.302 45.779,45.581 v2(46.725,45.581) ; U4.15@47.575,45.625 47.619,45.581 47.619,45.16 47.731,45.048 47.943,45.048 v2(47.951,45.04) 47.984,45.007 47.984,44.876 48.165,44.694 48.505,44.694 U4.11@48.55,44.65
  Mid-Layer 1 w0.125: v2@22.27,13.074 v2(22.26,13.064) 22.227,13.031 22.227,12.864 21.1,11.737 21.1,10.975 22.175,9.9 25.125,9.9 26.34,11.115 v2(26.34,11.6) ; v2(46.725,45.581) 47.41,45.581 v2(47.951,45.04)
  Bottom Layer w0.125: v1(31.876,15.397) 31.876,18.206 31.262,18.819 31.262,24.064 31.598,24.4 34.084,24.4 v1@34.434,24.75 ; v1(32.946,28.888) v1@34.447,28.888
  other v1: 34.5,24.75
UART0_RTS: U2.AL5 U3.3 | length 21.9
  Top Layer w0.125: v1(19.34,11.366) 19.797,11.823 19.797,12.23 20.059,12.492 U2.AL5@20.06,12.664 U2.AL5@20.06,12.664 ; v2(30.25,21.75) 30.85,21.15 U3.3@31.86,21.15
  Mid-Layer 1 w0.125: v1(28.675,15.05) 28.675,15.151 28.912,15.389 28.912,16.93 29.275,17.292 29.275,20.775 v2(30.25,21.75)
  Bottom Layer w0.125: v1(19.34,11.366) 19.797,11.823 19.797,12.246 20.477,12.926 24.676,12.926 26.375,14.625 27.898,14.625 28.315,15.042 28.667,15.042 v1(28.675,15.05)
UART0_RxD: U2.AL19 U3.4 | length 18.1
  Top Layer w0.125: U2.AL19@22.86,12.664 22.879,12.645 22.879,12.365 23.353,11.891 23.353,11.213 23.238,11.097 v2(23.238,11.05) ; v2(26.685,11.938) 27.113,11.938 27.2,12.025 29.125,13.95 29.125,15.853 29.25,15.978 v2(29.25,16.014) ; v2(30.751,20.757) 30.755,20.753 31.857,20.753 U3.4@31.86,20.75
  Mid-Layer 1 w0.125: v2(23.238,11.05) 23.46,11.273 23.46,11.834 23.883,12.257 26.366,12.257 v2(26.685,11.938) ; v2(29.25,16.014) 29.25,16.675 29.6,17.025 29.6,19.048 30.725,20.173 30.725,20.183 30.753,20.21 30.753,20.755 v2(30.751,20.757)
UART0_TxD: U2.U31 U3.2 | length 14
  Top Layer w0.125: U2.U31@25.46,15.664 25.665,15.664 26.429,14.9 27.784,14.9 28.048,15.164 v2(28.086,15.164) ; v2@29.8,22.825 31.075,21.55 U3.2@31.86,21.55
  Mid-Layer 1 w0.125: v2(28.086,15.164) 28.133,15.164 28.194,15.225 28.201,15.225 28.65,15.674 28.65,17.732 28.9,17.982 28.9,21.873 29.802,22.775 v2(29.802,22.823)
UART1_CTRL: R15.2 U2.AK18 U5.12 U6.1 U6.4 | length 69.9
  Top Layer w0.125: v3(22.163,10.65) 22.163,10.088 23.281,8.969 27.019,8.969 29.075,11.025 30.975,11.025 32.65,9.35 v1(33.115,9.35) v1(36.813,9.35) ; R15.2@32.285,28.253 R15.2@32.301,28.253 v1(33.412,28.253) ; U5.12@32.5,17.75 v1(32.5,18.75) ; v1(39.55,16.725) 39.55,16.826 39.725,17.001 39.725,26.3 ; 44.8,30.6 46.5,30.6 46.8,30.9 46.8,31.077 46.847,31.125 U6.4@47,31.125 ; U6.4@46.986,31.136 47.033,31.184 47.33,31.184 47.521,31.375 47.521,32.136 47.369,32.289 47.083,32.289 U6.1@47.036,32.336
  Top Layer w0.127: 39.725,26.3 v1(39.725,28.252) 39.725,29.175 41.15,30.6 44.8,30.6
  Mid-Layer 1 w0.125: v3(22.163,10.65) 22.143,10.67 22.143,10.995 22.062,11.076 22.062,12.235 22.66,12.834 v2(22.66,13.064)
  Bottom Layer w0.125: v1(32.5,18.75) 32.5,18.15 32.938,17.712 32.938,15.234 32.725,15.022 32.725,12.246 33.115,11.856 v1(33.115,9.35) ; v1(33.412,28.253) v1@39.649,28.252 ; v1(36.813,9.35) 36.825,9.362 36.825,12 37.537,12.712 37.537,15.787 38.475,16.725 v1(39.55,16.725)
UART1_CTS: U2.AL15 U5.5 | length 15.5
  Top Layer w0.125: U2.AL15@22.06,12.664 22.06,12.226 22.337,11.95 22.337,11.389 23.916,9.809 26.578,9.809 28.623,11.854 28.842,11.854 v2(28.875,11.888) ; 30.985,16.1 30.987,16.098 31.295,16.098 v2(31.297,16.096) ; v2@31.3,16.1 31.302,16.098 31.858,16.098 U5.5@31.86,16.1
  Mid-Layer 1 w0.125: v2(28.875,11.888) 28.875,11.898 30.108,13.13 30.108,13.643 30.983,14.519 30.983,15.782 v2(31.297,16.096)
UART1_HWFC: R16.2 U2.AK20 U6.11 U6.15 | length 57.9
  Top Layer w0.125: v3(22.54,10.25) 23.546,9.244 26.941,9.244 28.996,11.3 31.175,11.3 32.6,9.875 v1(35.925,9.875) ; R16.2@32.301,27.624 v1(32.941,27.624) ; v1(37.6,16.775) 39.213,18.388 ; 39.25,18.388 v1(39.25,27.637) 39.25,29.375 40.875,31 v2(45.1,31) ; U6.15@47.561,32.911 47.622,32.849 47.622,32.602 47.841,32.383 47.966,32.383 v2(48,32.35) 48.033,32.316 48.033,32.191 48.244,31.981 48.491,31.981 U6.11@48.536,31.936
  Mid-Layer 1 w0.125: v3(22.54,10.25) 22.54,11.01 22.4,11.15 22.4,12.162 23.06,12.822 v2(23.06,13.064) ; v2(45.1,31) 45.1,31.245 46.055,32.2 47.839,32.2 47.989,32.35 v2(48,32.35)
  Bottom Layer w0.125: v1@32.954,27.637 v1@39.2,27.637 ; v1(35.925,9.875) 36.507,10.457 36.507,15.682 v1(37.6,16.775)
UART1_RTS: U2.AL13 U5.3 | length 17.8
  Top Layer w0.125: U2.AL13@21.66,12.664 21.66,12.195 22.062,11.793 22.062,11.275 23.803,9.534 26.759,9.534 28.775,11.55 29.1,11.55 v3(29.4,11.85) ; v2(31.075,16.9) U5.3@31.86,16.9
  Mid-Layer 1 w0.125: v3(29.4,11.85) 30.475,12.925 30.475,13.657 31.233,14.415 31.233,15.373 31.7,15.84 31.7,16.525 31.325,16.9 v2(31.075,16.9)
UART1_RxD: U2.AL21 U5.4 | length 14.8
  Top Layer w0.125: U2.AL21@23.26,12.664 23.26,12.431 23.658,12.033 23.658,10.575 24.124,10.109 26.489,10.109 28.67,12.29 28.742,12.29 28.803,12.35 v2(28.85,12.35) ; v2(30.7,16.625) 30.747,16.625 30.872,16.5 U5.4@31.86,16.5
  Mid-Layer 1 w0.125: v2(28.85,12.35) 28.877,12.35 29.822,13.295 29.822,13.747 30.7,14.625 v2(30.7,16.625)
UART1_TxD: U2.AL23 U5.2 | length 14.7
  Top Layer w0.125: U2.AL23@23.66,12.664 23.671,12.654 23.671,12.457 23.963,12.165 23.963,10.697 24.276,10.384 26.375,10.384 28.956,12.965 29.015,12.965 v2(29.287,13.238) ; v2(30.35,17.3) U5.2@31.86,17.3
  Mid-Layer 1 w0.125: v2(29.287,13.238) 29.287,13.612 30.125,14.45 30.125,16.375 30.35,16.6 v2(30.35,17.3)
USB_DBGR.CC1: J3.A5 U10.23 | length 26.3
  Top Layer w0.125: v1(16.204,41.846) 16.847,41.846 17.342,42.341 17.342,44.442 17.493,44.593 17.989,44.593 U10.23@17.992,44.596
  Top Layer w0.15: J3.A5@7.485,25.384 v1@8.526,25.384
  Bottom Layer w0.125: v1(8.527,25.383) 8.527,25.451 8.72,25.644 8.72,26.483 11.475,29.239 11.475,39.575 13.746,41.846 v1(16.204,41.846)
USB_DBGR.CC2: J3.B5 U10.24 | length 29
  Top Layer w0.125: v1(16.642,41.243) 17.323,41.243 18.142,42.061 18.142,44.015 18.061,44.096 U10.24@17.992,44.096
  Top Layer w0.15: J3.B5@7.485,22.384 v1(8.529,22.384)
  Bottom Layer w0.125: v1(8.529,22.384) 8.538,22.384 9,22.846 9,26.3 11.8,29.1 11.8,39.4 13.643,41.243 v1(16.642,41.243)
VBUS: C23.2 C54.1 J4.5 R5.2 R36.2 SW4.4 TP8.1 U10.21 | length 137.9
  Top Layer w0.125: R5.2@28.512,9.889 R5.2@28.56,9.937 28.575,9.937 28.647,10.01 28.647,10.131 29.019,10.503 29.203,10.503 v1(29.275,10.575)
  Top Layer w0.2: R36.2@2.715,53.2 2.2,53.2 1.775,53.625 1.775,58.625 2.325,59.175 5.271,59.175 5.721,59.625 SW4.4@5.721,60.488
  Top Layer w0.3: C23.2@15.684,45.313 C23.2@15.702,45.295 ; C23.2@15.842,45.421 16.905,45.421 17.08,45.596 U10.21@17.992,45.596
  Top Layer w0.5: v1@8.35,51.468 v1(8.382,51.5)
  Top Layer w0.8: SW4.4@5.721,60.488 7.062,60.488 8.35,59.2 8.35,51.468 8.35,48.838 11.867,45.321 C54.1@14.742,45.321
  Bottom Layer w0.125: v1(26.958,2.074) 27.593,2.709 30.808,2.709 31.328,3.23 31.328,6.597 29.275,8.65 v1(29.275,10.575)
  Bottom Layer w0.25: v1(11.842,45.346) 9.071,45.346 4.575,40.85 4.575,13.825 11.55,6.85 11.55,2.645 11.842,2.354 18.039,2.354 18.993,1.4 26.284,1.4 v1(26.958,2.074)
  Bottom Layer w0.5: v1(8.382,51.5) 15.75,51.5 16.75,52.5 16.75,58.25 18,59.5 21.911,59.5 TP8.1@23.372,58.039
VBUS:IN: C30.1 C47.2 C48.2 FB3.1 J3.A4 J3.A9 TP16.1 U11.1 | length 7.2
  Top Layer w0.45: J3.A9@7.485,21.734 7.487,21.732 v1(8.517,21.732)
  Bottom Layer w0.45: v1(8.517,21.732) 8.519,21.73 12.548,21.73 13.263,22.446 TP16.1@13.263,23.571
